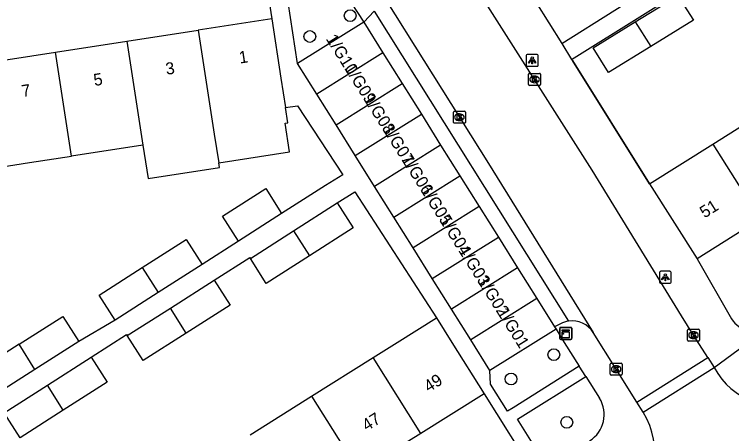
# Model space of a CAD drawing. Extents: x 160077 to 160945, y 386481 to 387498.
# Drawn here: x 160424.3 to 160484.1, y 387242.4 to 387277.3 of the extents above; entities that cross this region are included whole.
import ezdxf

# ---------------------------------------------------------------- set-up
doc = ezdxf.new("R2010")
doc.units = 0
for name, color, linetype in [('IMGEO_Boom', 7, 'Continuous'), ('IMGEO_Kast', 7, 'Continuous'), ('IMGEO_Kolk', 7, 'Continuous'), ('IMGEO_Lichtpunt', 7, 'Continuous'), ('IMGEO_Muur', 7, 'Continuous'), ('IMGEO_Pand', 7, 'Continuous'), ('IMGEO_Pand_nummerreeks', 7, 'Continuous'), ('IMGEO_Rijbaan_lokaal_open', 7, 'Continuous'), ('IMGEO_Voetpad_open', 7, 'Continuous')]:
    doc.layers.add(name, color=color, linetype=linetype)

msp = doc.modelspace()

# ---------------------------------------------------------------- linework, layer by layer
at = {"layer": 'IMGEO_Boom'}
for centre in [(160452.29, 387277.235), (160448.929, 387275.5), (160469.256, 387248.98), (160465.692, 387246.952), (160470.336, 387243.344)]:
    msp.add_circle(centre, 0.489, dxfattribs=at)
at = {"layer": 'IMGEO_Kast'}
for p, q in [((160469.746, 387250.334), (160469.746, 387251.175)), ((160469.746, 387251.175), (160469.746, 387250.334)), ((160469.821, 387251.259), (160470.662, 387251.259)), ((160470.662, 387251.259), (160469.821, 387251.259)), ((160470.746, 387251.184), (160470.746, 387250.343)), ((160470.746, 387250.343), (160470.746, 387251.184)), ((160470.671, 387250.259), (160469.83, 387250.259)), ((160469.83, 387250.259), (160470.671, 387250.259))]:
    msp.add_line(p, q, dxfattribs=at)
for points in [[(160469.941, 387251.049), (160470.541, 387251.049), (160470.541, 387250.964), (160469.941, 387250.964), (160469.941, 387251.049)], [(160469.941, 387250.874), (160470.541, 387250.874), (160470.541, 387250.385), (160469.941, 387250.385), (160469.941, 387250.874)]]:
    msp.add_lwpolyline(points, dxfattribs=at)
msp.add_circle((160470.025, 387250.723), 0.0377, dxfattribs=at)
for centre, start, end in [((160469.824, 387251.181), 92.4484, 184.28452), ((160469.824, 387251.181), 92.4484, 184.28452), ((160470.668, 387251.181), 2.4484, 94.28452), ((160470.668, 387251.181), 2.4484, 94.28452), ((160469.824, 387250.337), 182.4484, 274.28452), ((160469.824, 387250.337), 182.4484, 274.28452), ((160470.668, 387250.337), 272.4484, 4.28452), ((160470.668, 387250.337), 272.4484, 4.28452)]:
    msp.add_arc(centre, 0.0779, start, end, dxfattribs=at)
at = {"layer": 'IMGEO_Kolk'}
for p, q in [((160467.147, 387271.501), (160467.147, 387272.353)), ((160467.222, 387272.427), (160468.074, 387272.427)), ((160468.148, 387272.353), (160468.148, 387271.501)), ((160467.635, 387272.207), (160467.66, 387272.207)), ((160468.074, 387271.427), (160467.222, 387271.427)), ((160467.658, 387271.647), (160467.633, 387271.647)), ((160460.963, 387269.27), (160461.815, 387269.27)), ((160460.888, 387268.344), (160460.888, 387269.196)), ((160461.376, 387269.05), (160461.401, 387269.05)), ((160461.889, 387269.196), (160461.889, 387268.344)), ((160461.815, 387268.27), (160460.963, 387268.27)), ((160461.399, 387268.49), (160461.374, 387268.49)), ((160480.389, 387250.182), (160480.389, 387251.034)), ((160480.464, 387251.108), (160481.316, 387251.108)), ((160480.877, 387250.888), (160480.902, 387250.888)), ((160481.39, 387251.034), (160481.39, 387250.182)), ((160480.9, 387250.328), (160480.875, 387250.328)), ((160481.316, 387250.108), (160480.464, 387250.108)), ((160473.948, 387247.35), (160473.948, 387248.202)), ((160474.023, 387248.276), (160474.875, 387248.276)), ((160474.436, 387248.056), (160474.461, 387248.056)), ((160474.949, 387248.202), (160474.949, 387247.35)), ((160474.875, 387247.276), (160474.023, 387247.276)), ((160474.459, 387247.496), (160474.434, 387247.496))]:
    msp.add_line(p, q, dxfattribs=at)
for points in [[(160467.147, 387271.501), (160467.147, 387272.353)], [(160467.222, 387272.427), (160468.074, 387272.427)], [(160468.148, 387272.353), (160468.148, 387271.501)], [(160467.468, 387272.127), (160467.591, 387272.127), (160467.591, 387271.976), (160467.721, 387272.127), (160467.885, 387272.127), (160467.739, 387271.976), (160467.892, 387271.727), (160467.74, 387271.727), (160467.655, 387271.891), (160467.591, 387271.824), (160467.591, 387271.727), (160467.468, 387271.727), (160467.468, 387272.127)], [(160468.074, 387271.427), (160467.222, 387271.427)], [(160460.963, 387269.27), (160461.815, 387269.27)], [(160460.888, 387268.344), (160460.888, 387269.196)], [(160461.209, 387268.97), (160461.332, 387268.97), (160461.332, 387268.819), (160461.462, 387268.97), (160461.626, 387268.97), (160461.48, 387268.819), (160461.633, 387268.57), (160461.481, 387268.57), (160461.396, 387268.734), (160461.332, 387268.667), (160461.332, 387268.57), (160461.209, 387268.57), (160461.209, 387268.97)], [(160461.889, 387269.196), (160461.889, 387268.344)], [(160461.815, 387268.27), (160460.963, 387268.27)], [(160480.389, 387250.182), (160480.389, 387251.034)], [(160480.464, 387251.108), (160481.316, 387251.108)], [(160480.71, 387250.808), (160480.833, 387250.808), (160480.833, 387250.657), (160480.963, 387250.808), (160481.127, 387250.808), (160480.981, 387250.657), (160481.134, 387250.408), (160480.982, 387250.408), (160480.897, 387250.572), (160480.833, 387250.505), (160480.833, 387250.408), (160480.71, 387250.408), (160480.71, 387250.808)], [(160481.39, 387251.034), (160481.39, 387250.182)], [(160481.316, 387250.108), (160480.464, 387250.108)], [(160473.948, 387247.35), (160473.948, 387248.202)], [(160474.023, 387248.276), (160474.875, 387248.276)], [(160474.269, 387247.976), (160474.392, 387247.976), (160474.392, 387247.825), (160474.522, 387247.976), (160474.686, 387247.976), (160474.54, 387247.825), (160474.693, 387247.576), (160474.541, 387247.576), (160474.456, 387247.74), (160474.392, 387247.673), (160474.392, 387247.576), (160474.269, 387247.576), (160474.269, 387247.976)], [(160474.949, 387248.202), (160474.949, 387247.35)], [(160474.875, 387247.276), (160474.023, 387247.276)]]:
    msp.add_lwpolyline(points, dxfattribs=at)
for centre, start, end in [((160467.224, 387272.351), 91.55205, 178.44795), ((160467.224, 387272.351), 91.55205, 178.44795), ((160468.072, 387272.351), 1.55205, 88.44795), ((160468.072, 387272.351), 1.55205, 88.44795), ((160467.224, 387271.503), 181.55205, 268.44795), ((160467.224, 387271.503), 181.55205, 268.44795), ((160468.072, 387271.503), 271.55205, 358.44795), ((160468.072, 387271.503), 271.55205, 358.44795), ((160460.965, 387269.194), 91.55205, 178.44795), ((160460.965, 387269.194), 91.55205, 178.44795), ((160461.813, 387269.194), 1.55205, 88.44795), ((160461.813, 387269.194), 1.55205, 88.44795), ((160460.965, 387268.346), 181.55205, 268.44795), ((160460.965, 387268.346), 181.55205, 268.44795), ((160461.813, 387268.346), 271.55205, 358.44795), ((160461.813, 387268.346), 271.55205, 358.44795), ((160480.466, 387251.032), 91.55205, 178.44795), ((160480.466, 387251.032), 91.55205, 178.44795), ((160481.314, 387251.032), 1.55205, 88.44795), ((160481.314, 387251.032), 1.55205, 88.44795), ((160480.466, 387250.184), 181.55205, 268.44795), ((160480.466, 387250.184), 181.55205, 268.44795), ((160481.314, 387250.184), 271.55205, 358.44795), ((160481.314, 387250.184), 271.55205, 358.44795), ((160474.025, 387248.2), 91.55205, 178.44795), ((160474.025, 387248.2), 91.55205, 178.44795), ((160474.873, 387248.2), 1.55205, 88.44795), ((160474.873, 387248.2), 1.55205, 88.44795), ((160474.025, 387247.352), 181.55205, 268.44795), ((160474.025, 387247.352), 181.55205, 268.44795), ((160474.873, 387247.352), 271.55205, 358.44795), ((160474.873, 387247.352), 271.55205, 358.44795)]:
    msp.add_arc(centre, 0.0765, start, end, dxfattribs=at)
for centre, major_axis, ratio, start_param, end_param in [((160467.634, 387271.927), (-0.387, 0.002), 0.722429, 4.712389, 7.853982), ((160467.659, 387271.927), (-0.39, 0.002), 0.717154, 1.570796, 4.712389), ((160461.375, 387268.77), (-0.387, 0.002), 0.722429, 4.712389, 7.853982), ((160461.4, 387268.77), (-0.39, 0.002), 0.717154, 1.570796, 4.712389), ((160480.876, 387250.608), (-0.387, 0.002), 0.722429, 4.712389, 7.853982), ((160480.901, 387250.608), (-0.39, 0.002), 0.717154, 1.570796, 4.712389), ((160474.435, 387247.776), (-0.387, 0.002), 0.722429, 4.712389, 7.853982), ((160474.46, 387247.776), (-0.39, 0.002), 0.717154, 1.570796, 4.712389)]:
    msp.add_ellipse(centre, major_axis=major_axis, ratio=ratio, start_param=start_param, end_param=end_param, dxfattribs=at)
at = {"layer": 'IMGEO_Lichtpunt'}
for p, q in [((160466.953, 387273.915), (160466.953, 387273.108)), ((160466.953, 387273.915), (160466.953, 387273.108)), ((160467.855, 387274.01), (160467.047, 387274.01)), ((160467.855, 387274.01), (160467.047, 387274.01)), ((160467.949, 387273.108), (160467.949, 387273.915)), ((160467.949, 387273.108), (160467.949, 387273.915)), ((160467.047, 387273.014), (160467.855, 387273.014)), ((160467.047, 387273.014), (160467.855, 387273.014)), ((160478.046, 387255.832), (160478.046, 387255.025)), ((160478.046, 387255.832), (160478.046, 387255.025)), ((160478.948, 387255.927), (160478.14, 387255.927)), ((160478.948, 387255.927), (160478.14, 387255.927)), ((160479.042, 387255.025), (160479.042, 387255.832)), ((160479.042, 387255.025), (160479.042, 387255.832)), ((160478.14, 387254.931), (160478.948, 387254.931)), ((160478.14, 387254.931), (160478.948, 387254.931))]:
    msp.add_line(p, q, dxfattribs=at)
for points in [[(160467.327, 387273.579), (160467.366, 387273.551), (160467.178, 387273.289), (160467.14, 387273.316), (160467.327, 387273.579)], [(160467.429, 387273.531), (160467.476, 387273.531), (160467.476, 387273.209), (160467.429, 387273.209), (160467.429, 387273.531)], [(160467.539, 387273.551), (160467.577, 387273.578), (160467.764, 387273.316), (160467.725, 387273.288), (160467.539, 387273.551)], [(160478.42, 387255.496), (160478.459, 387255.468), (160478.271, 387255.206), (160478.233, 387255.233), (160478.42, 387255.496)], [(160478.522, 387255.448), (160478.569, 387255.448), (160478.569, 387255.126), (160478.522, 387255.126), (160478.522, 387255.448)], [(160478.632, 387255.468), (160478.67, 387255.495), (160478.857, 387255.233), (160478.818, 387255.205), (160478.632, 387255.468)]]:
    msp.add_lwpolyline(points, dxfattribs=at)
for centre in [(160467.452, 387273.713), (160478.545, 387255.63)]:
    msp.add_circle(centre, 0.0994, dxfattribs=at)
for centre, start, end in [((160467.047, 387273.915), 90, 180), ((160467.047, 387273.915), 90, 180), ((160467.855, 387273.915), 0, 90), ((160467.855, 387273.915), 0, 90), ((160467.047, 387273.108), 180, 270), ((160467.047, 387273.108), 180, 270), ((160467.855, 387273.108), 270, 0), ((160467.855, 387273.108), 270, 360), ((160478.14, 387255.832), 90, 180), ((160478.14, 387255.832), 90, 180), ((160478.948, 387255.832), 0, 90), ((160478.948, 387255.832), 0, 90), ((160478.14, 387255.025), 180, 270), ((160478.14, 387255.025), 180, 270), ((160478.948, 387255.025), 270, 0), ((160478.948, 387255.025), 270, 360)]:
    msp.add_arc(centre, 0.0946, start, end, dxfattribs=at)
at = {"layer": 'IMGEO_Muur'}
msp.add_lwpolyline([(160477.236, 387263.222), (160470.805, 387273.487)], dxfattribs=at)
at = {"layer": 'IMGEO_Pand'}
for points in [[(160476.033, 387276.718), (160479.598, 387278.921), (160480.876, 387276.853), (160477.328, 387274.661)], [(160445.762, 387276.968), (160439.635, 387276.024)], [(160445.762, 387276.968), (160446.524, 387272.027), (160446.901, 387269.58)], [(160453.415, 387276.694), (160447.912, 387273.249)], [(160453.415, 387276.694), (160455.018, 387274.134)], [(160477.328, 387274.661), (160473.814, 387272.489), (160472.536, 387274.557), (160476.033, 387276.718)], [(160476.033, 387276.718), (160477.328, 387274.661)], [(160433.686, 387275.107), (160439.635, 387276.024)], [(160439.635, 387276.024), (160440.971, 387267.357), (160441.339, 387264.971)], [(160427.738, 387274.191), (160433.686, 387275.107)], [(160433.686, 387275.107), (160435.022, 387266.44)], [(160421.789, 387273.274), (160427.738, 387274.191)], [(160429.074, 387265.524), (160427.738, 387274.191)], [(160455.018, 387274.134), (160449.514, 387270.689)], [(160455.018, 387274.134), (160456.62, 387271.574)], [(160449.514, 387270.689), (160447.912, 387273.249)], [(160451.117, 387268.129), (160456.62, 387271.574)], [(160456.62, 387271.574), (160458.222, 387269.014)], [(160451.117, 387268.129), (160449.514, 387270.689)], [(160441.339, 387264.971), (160447.246, 387265.881), (160446.878, 387268.267), (160447.098, 387268.301), (160446.901, 387269.58)], [(160482.499, 387266.536), (160487.612, 387269.756)], [(160452.719, 387265.569), (160458.222, 387269.014)], [(160458.222, 387269.014), (160459.825, 387266.454)], [(160452.719, 387265.569), (160451.117, 387268.129)], [(160435.022, 387266.44), (160429.074, 387265.524)], [(160435.022, 387266.44), (160435.452, 387263.653), (160441.401, 387264.571), (160441.339, 387264.971)], [(160459.825, 387266.454), (160454.322, 387263.009)], [(160459.825, 387266.454), (160461.428, 387263.894)], [(160477.236, 387263.222), (160482.499, 387266.536)], [(160482.499, 387266.536), (160486.446, 387260.269)], [(160423.125, 387264.607), (160425.582, 387264.986), (160429.074, 387265.524)], [(160454.322, 387263.009), (160452.719, 387265.569)], [(160455.924, 387260.449), (160461.428, 387263.894)], [(160461.428, 387263.894), (160463.03, 387261.333)], [(160442.995, 387258.447), (160441.665, 387260.53), (160445.268, 387262.83), (160446.581, 387260.737)], [(160455.924, 387260.449), (160454.322, 387263.009)], [(160477.236, 387263.222), (160481.183, 387256.955)], [(160447.575, 387259.301), (160451.218, 387261.627)], [(160451.218, 387261.627), (160452.547, 387259.544), (160448.888, 387257.207)], [(160463.03, 387261.333), (160457.526, 387257.888)], [(160463.03, 387261.333), (160464.632, 387258.773)], [(160446.581, 387260.737), (160442.995, 387258.447)], [(160457.526, 387257.888), (160455.924, 387260.449)], [(160486.446, 387260.269), (160481.183, 387256.955)], [(160443.973, 387257.001), (160447.575, 387259.301)], [(160447.575, 387259.301), (160448.888, 387257.207)], [(160434.975, 387256.244), (160438.618, 387258.57), (160439.947, 387256.487)], [(160459.129, 387255.328), (160464.632, 387258.773)], [(160464.632, 387258.773), (160466.235, 387256.213)], [(160459.129, 387255.328), (160457.526, 387257.888)], [(160448.888, 387257.207), (160445.303, 387254.918), (160443.973, 387257.001)], [(160432.703, 387251.861), (160431.373, 387253.944), (160434.975, 387256.244)], [(160434.975, 387256.244), (160436.288, 387254.151)], [(160439.947, 387256.487), (160436.288, 387254.151)], [(160466.235, 387256.213), (160460.731, 387252.768)], [(160466.235, 387256.213), (160467.838, 387253.653)], [(160437.322, 387252.869), (160440.965, 387255.195)], [(160440.965, 387255.195), (160442.294, 387253.112), (160438.635, 387250.776)], [(160460.731, 387252.768), (160459.129, 387255.328)], [(160436.288, 387254.151), (160432.703, 387251.861)], [(160467.838, 387253.653), (160462.334, 387250.208)], [(160467.838, 387253.653), (160469.313, 387251.296)], [(160433.72, 387250.569), (160437.322, 387252.869)], [(160438.635, 387250.776), (160437.322, 387252.869)], [(160462.334, 387250.208), (160460.731, 387252.768)], [(160424.711, 387249.844), (160428.354, 387252.169), (160429.683, 387250.086)], [(160454.2, 387248.74), (160456.208, 387250), (160459.474, 387252.049)], [(160459.474, 387252.049), (160460.76, 387250), (160463.439, 387245.729)], [(160438.635, 387250.776), (160435.05, 387248.486), (160433.72, 387250.569)], [(160469.44, 387251.093), (160463.936, 387247.648)], [(160469.313, 387251.296), (160469.44, 387251.093)], [(160463.936, 387247.648), (160462.334, 387250.208)], [(160424.711, 387249.844), (160421.109, 387247.543), (160422.351, 387245.598)], [(160426.025, 387247.75), (160424.711, 387249.844)], [(160429.683, 387250.086), (160426.025, 387247.75)], [(160427.07, 387246.436), (160430.712, 387248.762)], [(160430.712, 387248.762), (160432.041, 387246.679), (160428.383, 387244.343)], [(160449.074, 387245.524), (160454.2, 387248.74)], [(160458.165, 387242.42), (160454.2, 387248.74)], [(160426.025, 387247.75), (160422.439, 387245.46), (160422.351, 387245.598)], [(160423.467, 387244.136), (160427.07, 387246.436)], [(160428.383, 387244.343), (160427.07, 387246.436)], [(160443.947, 387242.308), (160449.074, 387245.524)], [(160449.074, 387245.524), (160453.038, 387239.204)], [(160463.439, 387245.729), (160458.165, 387242.42)], [(160428.383, 387244.343), (160424.797, 387242.053), (160423.467, 387244.136)], [(160458.165, 387242.42), (160453.038, 387239.204)]]:
    msp.add_lwpolyline(points, dxfattribs=at)
at = {"layer": 'IMGEO_Rijbaan_lokaal_open'}
for points in [[(160454.544, 387279.719), (160463.8, 387264.904), (160472.539, 387250.825)], [(160482.077, 387248.744), (160480.89, 387250.608), (160479.886, 387252.225), (160472.444, 387264.366), (160463.176, 387278.973)], [(160476.176, 387245.021), (160474.449, 387247.776), (160472.539, 387250.825)], [(160476.176, 387245.021), (160482.077, 387248.744)], [(160482.077, 387248.744), (160482.621, 387247.91)], [(160476.71, 387244.182), (160482.621, 387247.91)], [(160476.71, 387244.182), (160476.176, 387245.021)]]:
    msp.add_lwpolyline(points, dxfattribs=at)
for centre, radius, start, end in [((160487.8, 387250.574), 5.824, 207.21955, 294.4722), ((160471.277, 387240.834), 6.382, 306.66704, 31.64374)]:
    msp.add_arc(centre, radius, start, end, dxfattribs=at)
at = {"layer": 'IMGEO_Voetpad_open'}
for points in [[(160469.909, 387274.918), (160483.156, 387283.28), (160483.053, 387283.946)], [(160465.584, 387281.822), (160469.909, 387274.918)], [(160445.192, 387280.717), (160445.762, 387276.968)], [(160447.912, 387273.249), (160446.738, 387280.952)], [(160470.738, 387273.594), (160482.563, 387281.001)], [(160451.59, 387279.532), (160451.794, 387279.23), (160453.415, 387276.694)], [(160454.302, 387277.61), (160453.415, 387276.694)], [(160454.302, 387277.61), (160470.472, 387251.777)], [(160469.909, 387274.918), (160470.738, 387273.594)], [(160470.738, 387273.594), (160470.805, 387273.487), (160477.236, 387263.222)], [(160446.901, 387269.58), (160447.899, 387269.732), (160451.691, 387263.982), (160450.239, 387263.073), (160446.581, 387260.737)], [(160451.218, 387261.627), (160452.689, 387262.566), (160459.474, 387252.049)], [(160442.995, 387258.447), (160439.947, 387256.487)], [(160440.965, 387255.195), (160443.921, 387257.082), (160443.973, 387257.001)], [(160481.183, 387256.955), (160484.068, 387251.966)], [(160432.703, 387251.861), (160429.683, 387250.086)], [(160469.808, 387251.56), (160469.313, 387251.296)], [(160469.44, 387251.093), (160470.126, 387250), (160471.376, 387248.01)], [(160482.621, 387247.91), (160487.15, 387251.24)], [(160430.712, 387248.762), (160433.668, 387250.65), (160433.72, 387250.569)], [(160471.376, 387248.01), (160465.867, 387244.563), (160465.393, 387244.266), (160463.974, 387246.534), (160463.936, 387247.648)], [(160471.912, 387247.163), (160471.376, 387248.01)], [(160468.731, 387239.603), (160466.226, 387243.596), (160471.912, 387247.163)], [(160471.912, 387247.163), (160473.058, 387245.353)], [(160463.439, 387245.729), (160467.691, 387238.95)]]:
    msp.add_lwpolyline(points, dxfattribs=at)
for centre, radius, start, end in [((160485.966, 387253.118), 2.22, 211.25974, 302.23021), ((160470.79, 387249.678), 2.123, 98.62632, 117.56921), ((160470.775, 387249.715), 2.084, 32.17938, 98.36178), ((160470.863, 387243.989), 2.584, 302.08759, 31.86666)]:
    msp.add_arc(centre, radius, start, end, dxfattribs=at)

# ---------------------------------------------------------------- texts
at = {"layer": 'IMGEO_Pand_nummerreeks'}
for s, rotation, p in [('1/G10', 302.02657, (160450.233, 387275.309)), ('1', 8.76052, (160443.103, 387273.24)), ('3', 8.76052, (160436.991, 387272.298)), ('1/G09', 302.02657, (160451.765, 387272.86)), ('5', 8.76, (160430.991, 387271.374)), ('7', 8.76052, (160424.993, 387270.449)), ('1/G08', 302.02657, (160453.351, 387270.323)), ('1/G07', 302.02657, (160454.933, 387267.795)), ('1/G06', 302.02657, (160456.516, 387265.264)), ('1/G05', 302.02657, (160458.1, 387262.732)), ('51', 32.19916, (160481.808, 387260.326)), ('1/G04', 302.02657, (160459.683, 387260.201)), ('1/G03', 302.02657, (160461.266, 387257.67)), ('1/G02', 302.02657, (160462.846, 387255.144)), ('1/G01', 302.02813, (160464.492, 387252.514)), ('49', 32.10343, (160458.824, 387245.809)), ('47', 32.10343, (160453.673, 387242.577))]:
    msp.add_text(s, height=1, rotation=rotation, dxfattribs=at).set_placement(p)

doc.saveas('drawing.dxf')
